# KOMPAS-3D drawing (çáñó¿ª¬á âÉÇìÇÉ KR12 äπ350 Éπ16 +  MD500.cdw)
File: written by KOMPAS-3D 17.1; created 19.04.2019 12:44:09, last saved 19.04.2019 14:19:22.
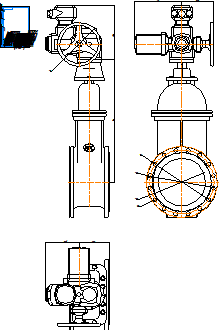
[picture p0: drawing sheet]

Sheet 1: A4, portrait

Title block, sheet 1: name: Задвижка ГРАНАР KR12 Ду350 Ру16 + / MD500; material: Внимание! Данный продукт является объектом авторского права ООО «Торговый Дом АДЛ». / Запрещается изменение, копирование, распространение / (в том числе путем копирования на другие сайты и ресурсы в Интернете) / или любое иное использование информации и объектов без предварительного / согласия правообладателя (ООО «Торговый Дом АДЛ»).; mass: 505,48; sheets: 1; organisation: ООО "Торговый дом АДЛ"; sheet format: A4; stored path: \\adlc.lan\data\АДЛ_ПКД\3D-модели\ADL production\Клиновые задвижки серии KR ГРАНАР\Клиновые задвижки KR12 с эл.приводами Смартгир\KOMPAS 2D\Задвижка ГРАНАР KR12 Ду350 Ру16 +  MD500.cdw

Views: Вид 1, Проекционный вид 3
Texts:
  user
Dimensions and other numbers on the sheet: 892; 391; 320; 520; 470; 241,19; 218,81; 1:1; 1; 505,48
